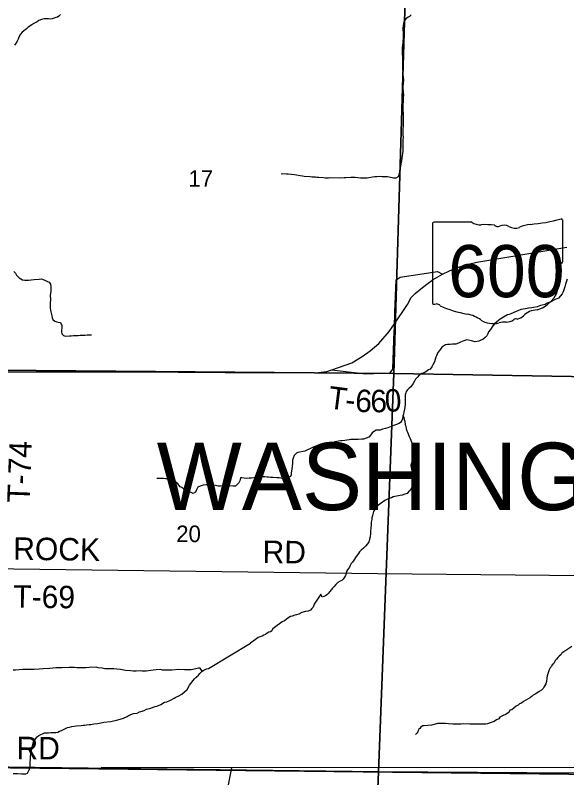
# Model space of a CAD drawing. Extents: x 1588073 to 2013523, y 1090242 to 1357120.
# Drawn here: x 1754621 to 1761986, y 1228620 to 1238801 of the extents above; entities that cross this region are included whole.
import ezdxf

# ---------------------------------------------------------------- set-up
doc = ezdxf.new("R2010")
doc.units = 0
for name, color, linetype in [('GM_X_County_Road', 7, 'Continuous'), ('GM_X_County_Road_Text', 7, 'Continuous'), ('GM_X_Minor_River', 7, 'Continuous'), ('GM_X_Section', 7, 'Continuous'), ('GM_X_Section_Text', 7, 'Continuous'), ('GM_X_State_Location', 7, 'Continuous'), ('GM_X_State_Route', 7, 'Continuous'), ('GM_X_State_Shield', 7, 'Continuous'), ('GM_X_Township_Road', 7, 'Continuous'), ('GM_X_Township_Road_Text', 7, 'Continuous'), ('GM_X_Township_Text', 7, 'Continuous')]:
    doc.layers.add(name, color=color, linetype=linetype)

msp = doc.modelspace()

# ---------------------------------------------------------------- linework, layer by layer
at = {"layer": 'GM_X_County_Road'}
msp.add_lwpolyline([(1754159, 1228756), (1764760, 1228634)], dxfattribs=at)
at = {"layer": 'GM_X_Minor_River'}
for p, q in [((1762696, 1228758), (1755770, 1228752)), ((1757461, 1228482), (1757515, 1228752))]:
    msp.add_line(p, q, dxfattribs=at)
for points in [[(1755225, 1238812), (1755205, 1238790), (1755185, 1238775), (1755165, 1238771), (1755139, 1238763), (1755115, 1238753), (1755091, 1238749), (1755067, 1238752), (1755033, 1238754), (1755007, 1238754), (1754971, 1238745), (1754934, 1238729), (1754912, 1238713), (1754870, 1238690), (1754844, 1238672), (1754795, 1238640), (1754769, 1238620), (1754715, 1238575), (1754690, 1238549), (1754668, 1238507), (1754658, 1238483), (1754645, 1238455), (1754633, 1238431), (1754611, 1238400)], [(1759907, 1238808), (1759888, 1238786), (1759868, 1238777), (1759838, 1238751), (1759816, 1238723), (1759807, 1238691), (1759801, 1238661), (1759799, 1238633), (1759799, 1238611), (1759800, 1238571), (1759802, 1238545), (1759801, 1238497), (1759797, 1238455), (1759795, 1238435), (1759792, 1238402), (1759790, 1238362), (1759789, 1238280), (1759791, 1238246), (1759792, 1238216), (1759792, 1238196), (1759794, 1238164), (1759793, 1238078), (1759795, 1238054), (1759796, 1238026), (1759798, 1238004), (1759802, 1237971), (1759804, 1237937), (1759803, 1237887), (1759799, 1237859), (1759798, 1237813), (1759800, 1237789), (1759802, 1237767), (1759804, 1237743), (1759803, 1237693), (1759801, 1237655), (1759796, 1237605), (1759796, 1237571), (1759797, 1237533), (1759801, 1237486), (1759801, 1237464), (1759802, 1237432), (1759801, 1237322), (1759799, 1237284), (1759796, 1237230), (1759798, 1237204), (1759800, 1237172), (1759799, 1237136), (1759797, 1237110), (1759797, 1237084), (1759796, 1237037), (1759796, 1236987), (1759793, 1236953), (1759787, 1236921), (1759783, 1236893), (1759778, 1236851), (1759772, 1236817), (1759764, 1236781), (1759757, 1236749), (1759753, 1236723), (1759747, 1236689), (1759742, 1236669), (1759734, 1236645), (1759704, 1236626), (1759674, 1236624), (1759614, 1236638), (1759594, 1236641), (1759566, 1236643), (1759520, 1236643)], [(1759520, 1236643), (1759492, 1236646), (1759448, 1236644), (1759422, 1236642), (1759390, 1236637), (1759342, 1236629), (1759320, 1236625), (1759272, 1236624), (1759252, 1236624), (1759232, 1236626), (1759194, 1236631), (1759162, 1236633), (1759124, 1236632), (1759102, 1236632), (1759038, 1236630), (1759015, 1236629), (1758959, 1236627), (1758835, 1236628), (1758805, 1236627), (1758761, 1236627), (1758739, 1236629), (1758677, 1236632), (1758649, 1236634), (1758629, 1236639), (1758609, 1236637), (1758587, 1236639), (1758561, 1236641), (1758481, 1236648), (1758459, 1236650), (1758427, 1236657), (1758375, 1236665), (1758351, 1236668), (1758305, 1236674), (1758265, 1236678), (1758243, 1236679), (1758193, 1236681), (1758173, 1236679)], [(1754603, 1235377), (1754625, 1235359), (1754639, 1235331), (1754673, 1235294), (1754716, 1235270), (1754750, 1235265), (1754774, 1235265), (1754796, 1235263), (1754834, 1235269), (1754873, 1235272), (1754941, 1235277), (1754973, 1235281), (1754995, 1235273), (1755023, 1235261), (1755052, 1235246), (1755074, 1235236), (1755092, 1235212), (1755098, 1235180), (1755097, 1235144), (1755095, 1235112), (1755091, 1235088), (1755088, 1235059), (1755090, 1235011), (1755089, 1234953), (1755087, 1234931), (1755089, 1234893), (1755092, 1234865), (1755096, 1234839), (1755110, 1234787), (1755115, 1234759), (1755121, 1234736), (1755151, 1234716), (1755175, 1234708), (1755195, 1234702)], [(1761994, 1235277), (1761983, 1235251), (1761971, 1235209), (1761960, 1235173), (1761940, 1235109), (1761927, 1235079), (1761875, 1235022), (1761831, 1235006), (1761766, 1234971), (1761724, 1234957), (1761696, 1234937), (1761658, 1234930), (1761634, 1234924), (1761593, 1234908), (1761543, 1234897), (1761521, 1234893), (1761477, 1234888), (1761457, 1234884), (1761437, 1234882), (1761373, 1234871), (1761333, 1234853), (1761311, 1234845), (1761238, 1234816), (1761218, 1234806), (1761194, 1234800), (1761142, 1234769), (1761095, 1234741), (1761073, 1234725), (1761049, 1234704), (1761027, 1234684), (1761000, 1234652), (1760968, 1234606), (1760942, 1234572), (1760933, 1234546), (1760917, 1234521), (1760897, 1234499), (1760864, 1234471), (1760838, 1234461), (1760810, 1234447), (1760762, 1234442), (1760712, 1234454), (1760676, 1234463), (1760652, 1234465), (1760610, 1234454), (1760590, 1234446), (1760566, 1234434), (1760540, 1234420), (1760504, 1234411), (1760461, 1234407), (1760431, 1234405), (1760395, 1234404), (1760367, 1234402), (1760341, 1234384), (1760319, 1234368), (1760299, 1234342), (1760287, 1234323), (1760264, 1234297), (1760248, 1234253)], [(1755195, 1234702), (1755227, 1234697), (1755242, 1234657), (1755242, 1234623), (1755240, 1234597), (1755240, 1234575), (1755245, 1234547), (1755267, 1234526), (1755291, 1234516), (1755347, 1234520), (1755369, 1234521), (1755399, 1234523), (1755461, 1234524), (1755489, 1234528), (1755555, 1234530), (1755581, 1234533), (1755639, 1234535)], [(1760248, 1234253), (1760238, 1234233), (1760219, 1234175), (1760198, 1234133), (1760184, 1234105), (1760160, 1234077), (1760140, 1234064), (1760103, 1234038), (1760083, 1234028), (1760049, 1234016), (1760015, 1233995), (1759987, 1233965), (1759966, 1233941), (1759954, 1233913), (1759936, 1233885), (1759903, 1233841), (1759881, 1233822), (1759861, 1233798), (1759843, 1233778), (1759838, 1233758), (1759830, 1233734), (1759830, 1233702), (1759827, 1233666), (1759827, 1233614), (1759822, 1233562), (1759818, 1233540), (1759812, 1233502), (1759805, 1233476), (1759799, 1233452), (1759793, 1233410), (1759784, 1233388), (1759766, 1233364), (1759746, 1233350), (1759714, 1233334), (1759684, 1233327), (1759642, 1233309), (1759621, 1233299), (1759597, 1233291), (1759565, 1233284), (1759527, 1233272), (1759493, 1233262), (1759467, 1233261), (1759441, 1233261), (1759417, 1233249), (1759389, 1233225), (1759370, 1233200), (1759342, 1233168), (1759308, 1233152), (1759274, 1233142), (1759248, 1233139), (1759199, 1233135), (1759161, 1233138), (1759135, 1233136), (1759103, 1233134), (1759081, 1233132), (1759049, 1233127), (1759021, 1233121), (1758983, 1233119), (1758963, 1233116), (1758891, 1233104), (1758871, 1233098), (1758843, 1233089), (1758821, 1233083), (1758793, 1233079), (1758748, 1233068), (1758714, 1233064), (1758678, 1233060), (1758646, 1233051), (1758592, 1233027), (1758564, 1233015), (1758517, 1232992), (1758487, 1232982), (1758465, 1232974), (1758417, 1232967), (1758395, 1232963), (1758375, 1232953), (1758347, 1232923), (1758334, 1232887), (1758324, 1232862), (1758322, 1232842), (1758322, 1232819), (1758317, 1232779), (1758313, 1232741), (1758308, 1232689), (1758306, 1232665), (1758298, 1232643), (1758270, 1232630), (1758239, 1232616), (1758209, 1232608), (1758173, 1232619), (1758147, 1232623), (1758115, 1232625), (1758063, 1232630), (1758031, 1232630), (1758005, 1232632), (1757985, 1232635), (1757955, 1232637), (1757923, 1232637), (1757895, 1232635), (1757871, 1232634), (1757833, 1232628)], [(1759800, 1233454), (1759809, 1233436), (1759815, 1233405), (1759822, 1233379), (1759830, 1233333), (1759838, 1233313), (1759843, 1233279), (1759851, 1233253), (1759861, 1233233), (1759880, 1233176), (1759894, 1233150), (1759904, 1233126), (1759921, 1233080), (1759939, 1233041), (1759949, 1233021), (1759953, 1232999), (1759954, 1232977), (1759956, 1232949), (1759956, 1232921), (1759950, 1232901), (1759937, 1232879), (1759927, 1232855), (1759911, 1232819), (1759906, 1232791), (1759910, 1232761), (1759912, 1232741), (1759918, 1232715), (1759931, 1232685), (1759941, 1232648), (1759947, 1232620), (1759944, 1232600), (1759940, 1232550), (1759928, 1232522), (1759921, 1232502), (1759895, 1232453), (1759873, 1232439), (1759854, 1232417), (1759826, 1232405), (1759790, 1232393), (1759762, 1232390), (1759738, 1232382), (1759692, 1232374), (1759668, 1232369), (1759646, 1232359), (1759612, 1232347), (1759583, 1232333), (1759557, 1232320), (1759509, 1232284), (1759489, 1232272), (1759458, 1232249), (1759438, 1232225), (1759420, 1232199), (1759406, 1232175), (1759393, 1232123), (1759383, 1232089), (1759381, 1232067), (1759374, 1232031), (1759374, 1231999), (1759369, 1231947), (1759367, 1231923), (1759365, 1231883), (1759360, 1231835), (1759354, 1231807), (1759343, 1231769), (1759327, 1231741), (1759297, 1231713), (1759273, 1231687), (1759240, 1231660), (1759220, 1231634), (1759206, 1231614), (1759189, 1231592), (1759163, 1231562), (1759153, 1231540), (1759126, 1231498), (1759108, 1231478), (1759094, 1231453), (1759084, 1231433), (1759057, 1231395), (1759047, 1231375), (1759039, 1231351), (1759031, 1231321), (1759020, 1231299), (1759002, 1231273), (1758984, 1231253), (1758960, 1231244), (1758928, 1231226), (1758901, 1231200), (1758881, 1231172), (1758859, 1231152), (1758838, 1231128), (1758824, 1231107), (1758802, 1231081), (1758784, 1231061), (1758764, 1231049), (1758721, 1231029), (1758700, 1231072), (1758629, 1230966), (1758614, 1230938), (1758600, 1230898), (1758584, 1230879), (1758563, 1230855)], [(1757833, 1232628), (1757775, 1232619), (1757747, 1232619), (1757709, 1232617), (1757677, 1232620), (1757649, 1232624), (1757627, 1232626), (1757625, 1232604), (1757621, 1232584), (1757608, 1232556), (1757584, 1232534), (1757564, 1232515), (1757532, 1232511), (1757452, 1232518), (1757428, 1232520), (1757384, 1232516), (1757362, 1232513), (1757330, 1232515), (1757296, 1232521), (1757266, 1232526), (1757236, 1232528), (1757198, 1232530), (1757164, 1232529), (1757130, 1232525), (1757092, 1232513), (1757059, 1232500), (1757037, 1232454), (1757027, 1232432), (1756996, 1232414), (1756931, 1232445), (1756901, 1232461), (1756869, 1232476), (1756845, 1232494), (1756825, 1232506), (1756794, 1232543), (1756764, 1232565), (1756744, 1232583), (1756680, 1232604), (1756650, 1232610), (1756628, 1232612), (1756602, 1232615), (1756578, 1232613), (1756532, 1232615), (1756512, 1232616)], [(1758563, 1230855), (1758531, 1230845), (1758495, 1230841), (1758449, 1230828), (1758407, 1230804), (1758375, 1230797), (1758355, 1230791), (1758318, 1230779), (1758296, 1230773), (1758260, 1230752), (1758216, 1230716), (1758186, 1230700), (1758151, 1230675), (1758121, 1230653), (1758101, 1230641), (1758081, 1230625), (1758058, 1230603), (1758048, 1230583), (1758028, 1230570), (1758008, 1230562), (1757984, 1230548), (1757962, 1230534), (1757942, 1230522), (1757917, 1230509), (1757889, 1230503), (1757865, 1230493), (1757762, 1230417)], [(1754592, 1228675), (1754649, 1228675), (1754705, 1228673), (1754761, 1228673), (1754785, 1228679), (1754813, 1228736), (1754821, 1228770), (1754822, 1228798), (1754822, 1228832), (1754824, 1228864), (1754826, 1228900), (1754828, 1228938), (1754834, 1228976), (1754842, 1229003), (1754846, 1229027), (1754854, 1229057), (1754860, 1229085), (1754874, 1229109), (1754894, 1229145), (1754912, 1229167), (1754936, 1229183), (1754964, 1229195), (1754986, 1229207), (1755010, 1229218), (1755032, 1229218), (1755064, 1229220), (1755094, 1229222), (1755136, 1229224), (1755162, 1229224), (1755188, 1229230), (1755210, 1229242), (1755238, 1229252), (1755266, 1229264), (1755320, 1229291), (1755344, 1229297), (1755376, 1229303), (1755440, 1229311), (1755502, 1229319), (1755528, 1229321), (1755550, 1229323), (1755574, 1229325), (1755606, 1229330), (1755632, 1229332), (1755670, 1229338), (1755718, 1229342), (1755784, 1229358), (1755806, 1229362), (1755897, 1229372), (1755993, 1229393), (1756065, 1229417), (1756115, 1229439), (1756143, 1229455), (1756201, 1229476), (1756247, 1229484), (1756281, 1229500), (1756315, 1229508), (1756343, 1229518), (1756375, 1229534), (1756433, 1229548), (1756463, 1229563), (1756491, 1229569), (1756523, 1229581), (1756563, 1229599), (1756615, 1229627), (1756645, 1229635), (1756695, 1229657), (1756741, 1229682), (1756767, 1229696), (1756807, 1229714), (1756847, 1229736), (1756883, 1229768), (1756919, 1229798), (1756949, 1229855), (1757013, 1229939), (1757037, 1229961), (1757067, 1229987), (1757087, 1230011), (1757119, 1230044), (1757141, 1230056), (1757173, 1230076), (1757203, 1230080), (1757762, 1230417)], [(1762056, 1230370), (1761921, 1230284), (1761912, 1230264), (1761885, 1230241), (1761867, 1230225), (1761849, 1230205), (1761836, 1230190), (1761819, 1230160), (1761809, 1230140), (1761793, 1230129), (1761782, 1230103), (1761766, 1230087), (1761753, 1230062), (1761745, 1230048), (1761732, 1230006), (1761727, 1229982), (1761720, 1229948), (1761720, 1229934), (1761717, 1229920), (1761717, 1229906), (1761706, 1229872), (1761681, 1229827), (1761671, 1229813), (1761650, 1229789), (1761618, 1229770), (1761599, 1229757), (1761565, 1229734), (1761538, 1229724), (1761526, 1229710), (1761504, 1229691), (1761439, 1229655), (1761410, 1229637), (1761381, 1229616), (1761357, 1229606), (1761339, 1229589), (1761312, 1229576), (1761282, 1229552), (1761251, 1229527), (1761227, 1229520), (1761212, 1229490), (1761176, 1229469), (1761129, 1229448), (1761094, 1229427), (1761078, 1229405), (1761048, 1229394), (1761015, 1229369), (1760962, 1229354), (1760928, 1229341), (1760906, 1229337), (1760854, 1229335), (1760788, 1229334), (1760692, 1229335), (1760612, 1229339), (1760577, 1229336), (1760519, 1229333), (1760465, 1229336), (1760405, 1229340), (1760369, 1229343), (1760315, 1229344), (1760279, 1229345), (1760261, 1229344), (1760245, 1229340), (1760181, 1229322), (1760080, 1229314), (1760062, 1229313), (1760038, 1229293), (1760023, 1229278), (1760009, 1229266), (1760003, 1229252), (1759998, 1229232), (1759986, 1229214), (1759965, 1229195)], [(1757119, 1230044), (1757092, 1230084), (1757066, 1230082), (1757034, 1230076), (1756970, 1230059), (1756880, 1230059), (1756806, 1230067), (1756712, 1230057), (1756688, 1230058), (1756650, 1230058), (1756586, 1230056), (1756562, 1230064), (1756504, 1230060), (1756464, 1230054), (1756369, 1230044), (1756317, 1230043), (1756291, 1230045), (1756237, 1230043), (1756195, 1230043), (1756163, 1230045), (1756095, 1230051), (1756025, 1230065), (1755979, 1230071), (1755939, 1230076), (1755816, 1230076), (1755782, 1230082), (1755726, 1230088), (1755700, 1230094), (1755606, 1230090), (1755562, 1230089), (1755478, 1230087), (1755444, 1230087), (1755412, 1230091), (1755342, 1230093), (1755248, 1230089), (1755163, 1230088), (1755083, 1230080), (1754993, 1230072), (1754939, 1230070), (1754875, 1230065), (1754781, 1230065), (1754743, 1230065), (1754719, 1230065), (1754623, 1230057), (1754593, 1230055)]]:
    msp.add_lwpolyline(points, dxfattribs=at)
at = {"layer": 'GM_X_Section'}
for points in [[(1754527, 1239348), (1759839, 1239306), (1759679, 1234018), (1754367, 1234062)], [(1759839, 1239306), (1765143, 1239225), (1764954, 1233927), (1759679, 1234018)], [(1754367, 1234062), (1759679, 1234018), (1759470, 1228698), (1754180, 1228767)], [(1759679, 1234018), (1764954, 1233927), (1764763, 1228664), (1759470, 1228698)], [(1754180, 1228767), (1759470, 1228698), (1759261, 1223437), (1753948, 1223482)], [(1764763, 1228664), (1764527, 1223413), (1759261, 1223437), (1759470, 1228698)]]:
    msp.add_lwpolyline(points, close=True, dxfattribs=at)
at = {"layer": 'GM_X_State_Route'}
msp.add_lwpolyline([(1754354, 1234040), (1756167, 1234039), (1758053, 1234025), (1758666, 1234030), (1758782, 1234044), (1758850, 1234066), (1759114, 1234161), (1759254, 1234242), (1759363, 1234319), (1759475, 1234419), (1759616, 1234578), (1759687, 1234682), (1759859, 1234939), (1759910, 1235031), (1759964, 1235085), (1760036, 1235149), (1760116, 1235212), (1760202, 1235271), (1760327, 1235343), (1760419, 1235388), (1760527, 1235433), (1760656, 1235473), (1760787, 1235503), (1761988, 1235705)], dxfattribs=at)
at = {"layer": 'GM_X_State_Shield'}
for p, q in [((1760192, 1236018), (1760192, 1234962)), ((1760719, 1236036), (1760209, 1236036)), ((1761932, 1235510), (1761932, 1236063)), ((1761932, 1235510), (1761932, 1235510))]:
    msp.add_line(p, q, dxfattribs=at)
for centre, major_axis, start_param, end_param in [((1760212, 1236020), (20.2, 0), 1.712693, 3.28349), ((1760840, 1236159), (196, 0), 4.042523, 4.731795), ((1760905, 1235443), (702, 0), 1.404758, 1.657858), ((1761064, 1236026), (56.4, 0), 3.836095, 5.185415), ((1761147, 1235904), (117, 0), 0.950623, 2.079405), ((1761547, 1235714), (371, 0), 1.699011, 2.107814), ((1761312, 1237477), (1845, 0), 4.814394, 5.042369), ((1761913, 1236065), (19.4, 0), 6.141152, 7.989035), ((1761298, 1236071), (141, 0), 4.081561, 5.145723), ((1761927, 1235469), (30, 0), 1.883978, 3.671073), ((1761911, 1235508), (20.7, 0), 5.05454, 6.418171), ((1761737, 1235399), (180, 0), 5.934695, 6.695948), ((1762001, 1235279), (131, 0), 2.387724, 3.262537), ((1761415, 1235208), (462, 0), 5.101752, 6.440018), ((1760212, 1234959), (20.3, 0), 3.00124, 4.508301), ((1760215, 1235067), (155, 0), 4.665946, 4.897461), ((1760247, 1234901), (56, 0), 0.519207, 1.627899), ((1760953, 1235850), (1333, 0), 4.195997, 4.488961), ((1761610, 1234665), (253, 0), 1.647645, 2.488434), ((1760556, 1234487), (417, 0), 0.823519, 1.323587), ((1761290, 1234859), (149, 0), 4.937069, 5.64225), ((1761007, 1234895), (265, 0), 4.026481, 4.996735), ((1761160, 1234530), (217, 0), 1.495662, 1.94098), ((1761179, 1234816), (141, 0), 4.691044, 5.507374), ((1761307, 1234714), (39.7, 0), 1.147584, 2.315152)]:
    msp.add_ellipse(centre, major_axis=major_axis, ratio=0.8, start_param=start_param, end_param=end_param, dxfattribs=at)
at = {"layer": 'GM_X_Township_Road'}
for points in [[(1759691, 1234789), (1759692, 1234833), (1759709, 1235266), (1759760, 1235303), (1760262, 1235381), (1760327, 1235343)], [(1759683, 1234583), (1759684, 1234627), (1759687, 1234682), (1759691, 1234789)], [(1758850, 1234066), (1759297, 1234013), (1759628, 1234026), (1759663, 1234075), (1759683, 1234583)], [(1754249, 1231414), (1759465, 1231348), (1761757, 1231324), (1764857, 1231313)]]:
    msp.add_lwpolyline(points, dxfattribs=at)

# ---------------------------------------------------------------- texts
at = {"layer": 'GM_X_County_Road_Text'}
msp.add_text('RD', height=300, rotation=359.5064, dxfattribs=at).set_placement((1754636, 1228868))
at = {"layer": 'GM_X_Section_Text'}
for s, p in [('17', (1756934, 1236510)), ('20', (1756771, 1231766))]:
    msp.add_text(s, height=221, rotation=0, dxfattribs=at).set_placement(p)
at = {"layer": 'GM_X_State_Location'}
for s in ['s', 'r']:
    msp.add_text(s, height=1, dxfattribs=at).set_placement((1761042, 1235420))
msp.add_text('600', height=1, rotation=0, dxfattribs=at).set_placement((1760689, 1235347))
at = {"layer": 'GM_X_State_Shield'}
msp.add_text('600', height=696.1, dxfattribs=at).set_placement((1760403, 1235036))
at = {"layer": 'GM_X_Township_Road_Text'}
for s, rotation, p in [('T', 352.7639, (1758788, 1233553)), ('6', 356.3651, (1759154, 1233509)), ('6', 1.2798, (1759366, 1233497)), ('0', 3.6881, (1759565, 1233502)), ('-', 353.7601, (1759016, 1233524)), ('T-74', 87.8787, (1754812, 1232286)), ('ROCK', 359.2595, (1754592, 1231530)), ('RD', 359.5063, (1757923, 1231486)), ('T-69', 359.2931, (1754593, 1230891))]:
    msp.add_text(s, height=300, rotation=rotation, dxfattribs=at).set_placement(p)
at = {"layer": 'GM_X_Township_Text'}
msp.add_text('WASHINGTON', height=900, rotation=0, dxfattribs=at).set_placement((1756511, 1232193))

doc.saveas('drawing.dxf')
